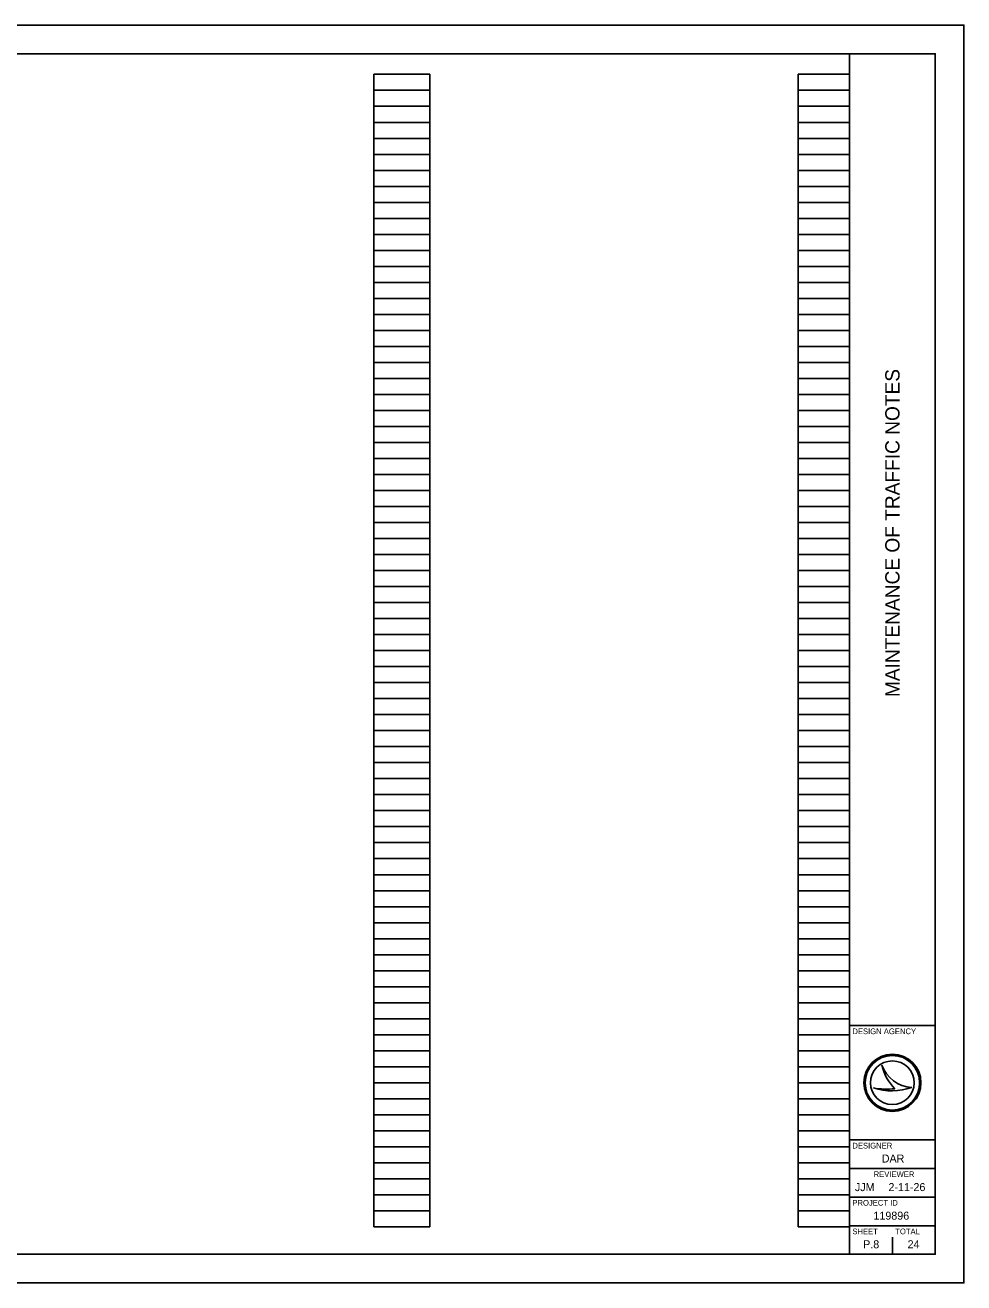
# Model space of a CAD drawing. Extents: x 0 to 34, y 0 to 22.
# Drawn here: x 17.58 to 34, y 0 to 22 of the extents above; entities that cross this region are included whole.
import ezdxf

# ---------------------------------------------------------------- set-up
doc = ezdxf.new("R2010")
doc.units = 0
for name, color, linetype in [('SH_Border', 7, 'Continuous'), ('SH_Cut_Line', 7, 'Continuous'), ('SH_Data', 7, 'Continuous')]:
    doc.layers.add(name, color=color, linetype=linetype)

msp = doc.modelspace()

# ---------------------------------------------------------------- linework, layer by layer
at = {"layer": 'SH_Border'}
for p, q in [((32, 0.5), (32, 21.5)), ((32, 4.5), (33.5, 4.5)), ((32, 2.5), (33.5, 2.5)), ((32, 2), (33.5, 2)), ((32, 1.5), (33.5, 1.5)), ((32, 1), (33.5, 1))]:
    msp.add_line(p, q, dxfattribs=at)
msp.add_lwpolyline([(1.5, 21.5), (33.5, 21.5), (33.5, 0.5), (1.5, 0.5)], close=True, dxfattribs=at)
at = {"layer": 'SH_Cut_Line'}
msp.add_lwpolyline([(0, 0), (34, 0), (34, 22), (0, 22)], close=True, dxfattribs=at)
at = {"layer": 'SH_Data'}
for p, q in [((23.68, 0.98), (23.68, 21.14)), ((23.68, 21.14), (24.66, 21.14)), ((24.66, 0.98), (24.66, 21.14)), ((31.1, 0.98), (31.1, 21.14)), ((31.1, 21.14), (32, 21.14)), ((32, 0.98), (32, 21.14)), ((23.68, 20.86), (24.66, 20.86)), ((31.1, 20.86), (32, 20.86)), ((23.68, 20.58), (24.66, 20.58)), ((31.1, 20.58), (32, 20.58)), ((23.68, 20.3), (24.66, 20.3)), ((31.1, 20.3), (32, 20.3)), ((23.68, 20.02), (24.66, 20.02)), ((31.1, 20.02), (32, 20.02)), ((23.68, 19.74), (24.66, 19.74)), ((31.1, 19.74), (32, 19.74)), ((23.68, 19.46), (24.66, 19.46)), ((31.1, 19.46), (32, 19.46)), ((23.68, 19.18), (24.66, 19.18)), ((31.1, 19.18), (32, 19.18)), ((23.68, 18.9), (24.66, 18.9)), ((31.1, 18.9), (32, 18.9)), ((23.68, 18.62), (24.66, 18.62)), ((31.1, 18.62), (32, 18.62)), ((23.68, 18.34), (24.66, 18.34)), ((31.1, 18.34), (32, 18.34)), ((23.68, 18.06), (24.66, 18.06)), ((31.1, 18.06), (32, 18.06)), ((23.68, 17.78), (24.66, 17.78)), ((31.1, 17.78), (32, 17.78)), ((23.68, 17.5), (24.66, 17.5)), ((31.1, 17.5), (32, 17.5)), ((23.68, 17.22), (24.66, 17.22)), ((31.1, 17.22), (32, 17.22)), ((23.68, 16.94), (24.66, 16.94)), ((31.1, 16.94), (32, 16.94)), ((23.68, 16.66), (24.66, 16.66)), ((31.1, 16.66), (32, 16.66)), ((23.68, 16.38), (24.66, 16.38)), ((31.1, 16.38), (32, 16.38)), ((23.68, 16.1), (24.66, 16.1)), ((31.1, 16.1), (32, 16.1)), ((23.68, 15.82), (24.66, 15.82)), ((31.1, 15.82), (32, 15.82)), ((23.68, 15.54), (24.66, 15.54)), ((31.1, 15.54), (32, 15.54)), ((23.68, 15.26), (24.66, 15.26)), ((31.1, 15.26), (32, 15.26)), ((23.68, 14.98), (24.66, 14.98)), ((31.1, 14.98), (32, 14.98)), ((23.68, 14.7), (24.66, 14.7)), ((31.1, 14.7), (32, 14.7)), ((23.68, 14.42), (24.66, 14.42)), ((31.1, 14.42), (32, 14.42)), ((23.68, 14.14), (24.66, 14.14)), ((31.1, 14.14), (32, 14.14)), ((23.68, 13.86), (24.66, 13.86)), ((31.1, 13.86), (32, 13.86)), ((23.68, 13.58), (24.66, 13.58)), ((31.1, 13.58), (32, 13.58)), ((23.68, 13.3), (24.66, 13.3)), ((31.1, 13.3), (32, 13.3)), ((23.68, 13.02), (24.66, 13.02)), ((31.1, 13.02), (32, 13.02)), ((23.68, 12.74), (24.66, 12.74)), ((31.1, 12.74), (32, 12.74)), ((23.68, 12.46), (24.66, 12.46)), ((31.1, 12.46), (32, 12.46)), ((23.68, 12.18), (24.66, 12.18)), ((31.1, 12.18), (32, 12.18)), ((23.68, 11.9), (24.66, 11.9)), ((31.1, 11.9), (32, 11.9)), ((23.68, 11.62), (24.66, 11.62)), ((31.1, 11.62), (32, 11.62)), ((23.68, 11.34), (24.66, 11.34)), ((31.1, 11.34), (32, 11.34)), ((23.68, 11.06), (24.66, 11.06)), ((31.1, 11.06), (32, 11.06)), ((23.68, 10.78), (24.66, 10.78)), ((31.1, 10.78), (32, 10.78)), ((23.68, 10.5), (24.66, 10.5)), ((31.1, 10.5), (32, 10.5)), ((23.68, 10.22), (24.66, 10.22)), ((31.1, 10.22), (32, 10.22)), ((23.68, 9.94), (24.66, 9.94)), ((31.1, 9.94), (32, 9.94)), ((23.68, 9.66), (24.66, 9.66)), ((31.1, 9.66), (32, 9.66)), ((23.68, 9.38), (24.66, 9.38)), ((31.1, 9.38), (32, 9.38)), ((23.68, 9.1), (24.66, 9.1)), ((31.1, 9.1), (32, 9.1)), ((23.68, 8.82), (24.66, 8.82)), ((31.1, 8.82), (32, 8.82)), ((23.68, 8.54), (24.66, 8.54)), ((31.1, 8.54), (32, 8.54)), ((23.68, 8.26), (24.66, 8.26)), ((31.1, 8.26), (32, 8.26)), ((23.68, 7.98), (24.66, 7.98)), ((31.1, 7.98), (32, 7.98)), ((23.68, 7.7), (24.66, 7.7)), ((31.1, 7.7), (32, 7.7)), ((23.68, 7.42), (24.66, 7.42)), ((31.1, 7.42), (32, 7.42)), ((23.68, 7.14), (24.66, 7.14)), ((31.1, 7.14), (32, 7.14)), ((23.68, 6.86), (24.66, 6.86)), ((31.1, 6.86), (32, 6.86)), ((23.68, 6.58), (24.66, 6.58)), ((31.1, 6.58), (32, 6.58)), ((23.68, 6.3), (24.66, 6.3)), ((31.1, 6.3), (32, 6.3)), ((23.68, 6.02), (24.66, 6.02)), ((31.1, 6.02), (32, 6.02)), ((23.68, 5.74), (24.66, 5.74)), ((31.1, 5.74), (32, 5.74)), ((23.68, 5.46), (24.66, 5.46)), ((31.1, 5.46), (32, 5.46)), ((23.68, 5.18), (24.66, 5.18)), ((31.1, 5.18), (32, 5.18)), ((23.68, 4.9), (24.66, 4.9)), ((31.1, 4.9), (32, 4.9)), ((23.68, 4.62), (24.66, 4.62)), ((31.1, 4.62), (32, 4.62)), ((23.68, 4.34), (24.66, 4.34)), ((31.1, 4.34), (32, 4.34)), ((23.68, 4.06), (24.66, 4.06)), ((31.1, 4.06), (32, 4.06)), ((23.68, 3.78), (24.66, 3.78)), ((31.1, 3.78), (32, 3.78)), ((32.567, 3.81), (32.567, 3.81)), ((23.68, 3.5), (24.66, 3.5)), ((31.1, 3.5), (32, 3.5)), ((32.417, 3.41), (32.417, 3.41)), ((32.75, 3.5), (32.75, 3.5)), ((33.087, 3.419), (33.087, 3.419)), ((23.68, 3.22), (24.66, 3.22)), ((31.1, 3.22), (32, 3.22)), ((23.68, 2.94), (24.66, 2.94)), ((31.1, 2.94), (32, 2.94)), ((23.68, 2.66), (24.66, 2.66)), ((31.1, 2.66), (32, 2.66)), ((23.68, 2.38), (24.66, 2.38)), ((31.1, 2.38), (32, 2.38)), ((23.68, 2.1), (24.66, 2.1)), ((31.1, 2.1), (32, 2.1)), ((23.68, 1.82), (24.66, 1.82)), ((31.1, 1.82), (32, 1.82)), ((23.68, 1.54), (24.66, 1.54)), ((31.1, 1.54), (32, 1.54)), ((23.68, 1.26), (24.66, 1.26)), ((31.1, 1.26), (32, 1.26)), ((23.68, 0.98), (24.66, 0.98)), ((31.1, 0.98), (32, 0.98)), ((32.375, 0.675), (32.375, 0.675)), ((32.75, 0.5), (32.75, 0.8))]:
    msp.add_line(p, q, dxfattribs=at)
for radius in [0.5, 0.477, 0.477, 0.382]:
    msp.add_circle((32.75, 3.5), radius, dxfattribs=at)
for centre, radius, start, end in [((33.116, 3.998), 0.58, 198.9257, 198.9319), ((33.347, 3.97), 0.796, 191.6379, 191.6421), ((33.116, 3.998), 0.58, 198.9319, 267.1657), ((33.347, 3.97), 0.796, 191.6421, 226.0947), ((32.739, 4.37), 1.013, 251.4576, 290.0832), ((32.648, 4.654), 1.266, 259.4964, 259.4995), ((32.739, 4.37), 1.013, 251.4527, 251.4576), ((32.648, 4.654), 1.266, 259.4995, 276.6672)]:
    msp.add_arc(centre, radius, start, end, dxfattribs=at)

# ---------------------------------------------------------------- texts
msp.add_text('MAINTENANCE OF TRAFFIC NOTES', height=0.25, rotation=90, dxfattribs=at).set_placement((32.875, 10.247))
for s, height, p in [('DESIGN AGENCY', 0.1, (32.05, 4.35)), ('DESIGNER', 0.1, (32.05, 2.35)), ('DAR', 0.14, (32.564, 2.105)), ('REVIEWER', 0.1, (32.422, 1.85)), ('JJM', 0.14, (32.095, 1.605)), ('2-11-26', 0.14, (32.682, 1.605)), ('PROJECT ID', 0.1, (32.05, 1.35)), ('119896', 0.14, (32.419, 1.105)), ('SHEET', 0.1, (32.05, 0.85)), ('TOTAL', 0.1, (32.8, 0.85)), ('P.8', 0.14, (32.239, 0.605)), ('24', 0.14, (33.016, 0.605))]:
    msp.add_text(s, height=height, dxfattribs=at).set_placement(p)

doc.saveas('drawing.dxf')
